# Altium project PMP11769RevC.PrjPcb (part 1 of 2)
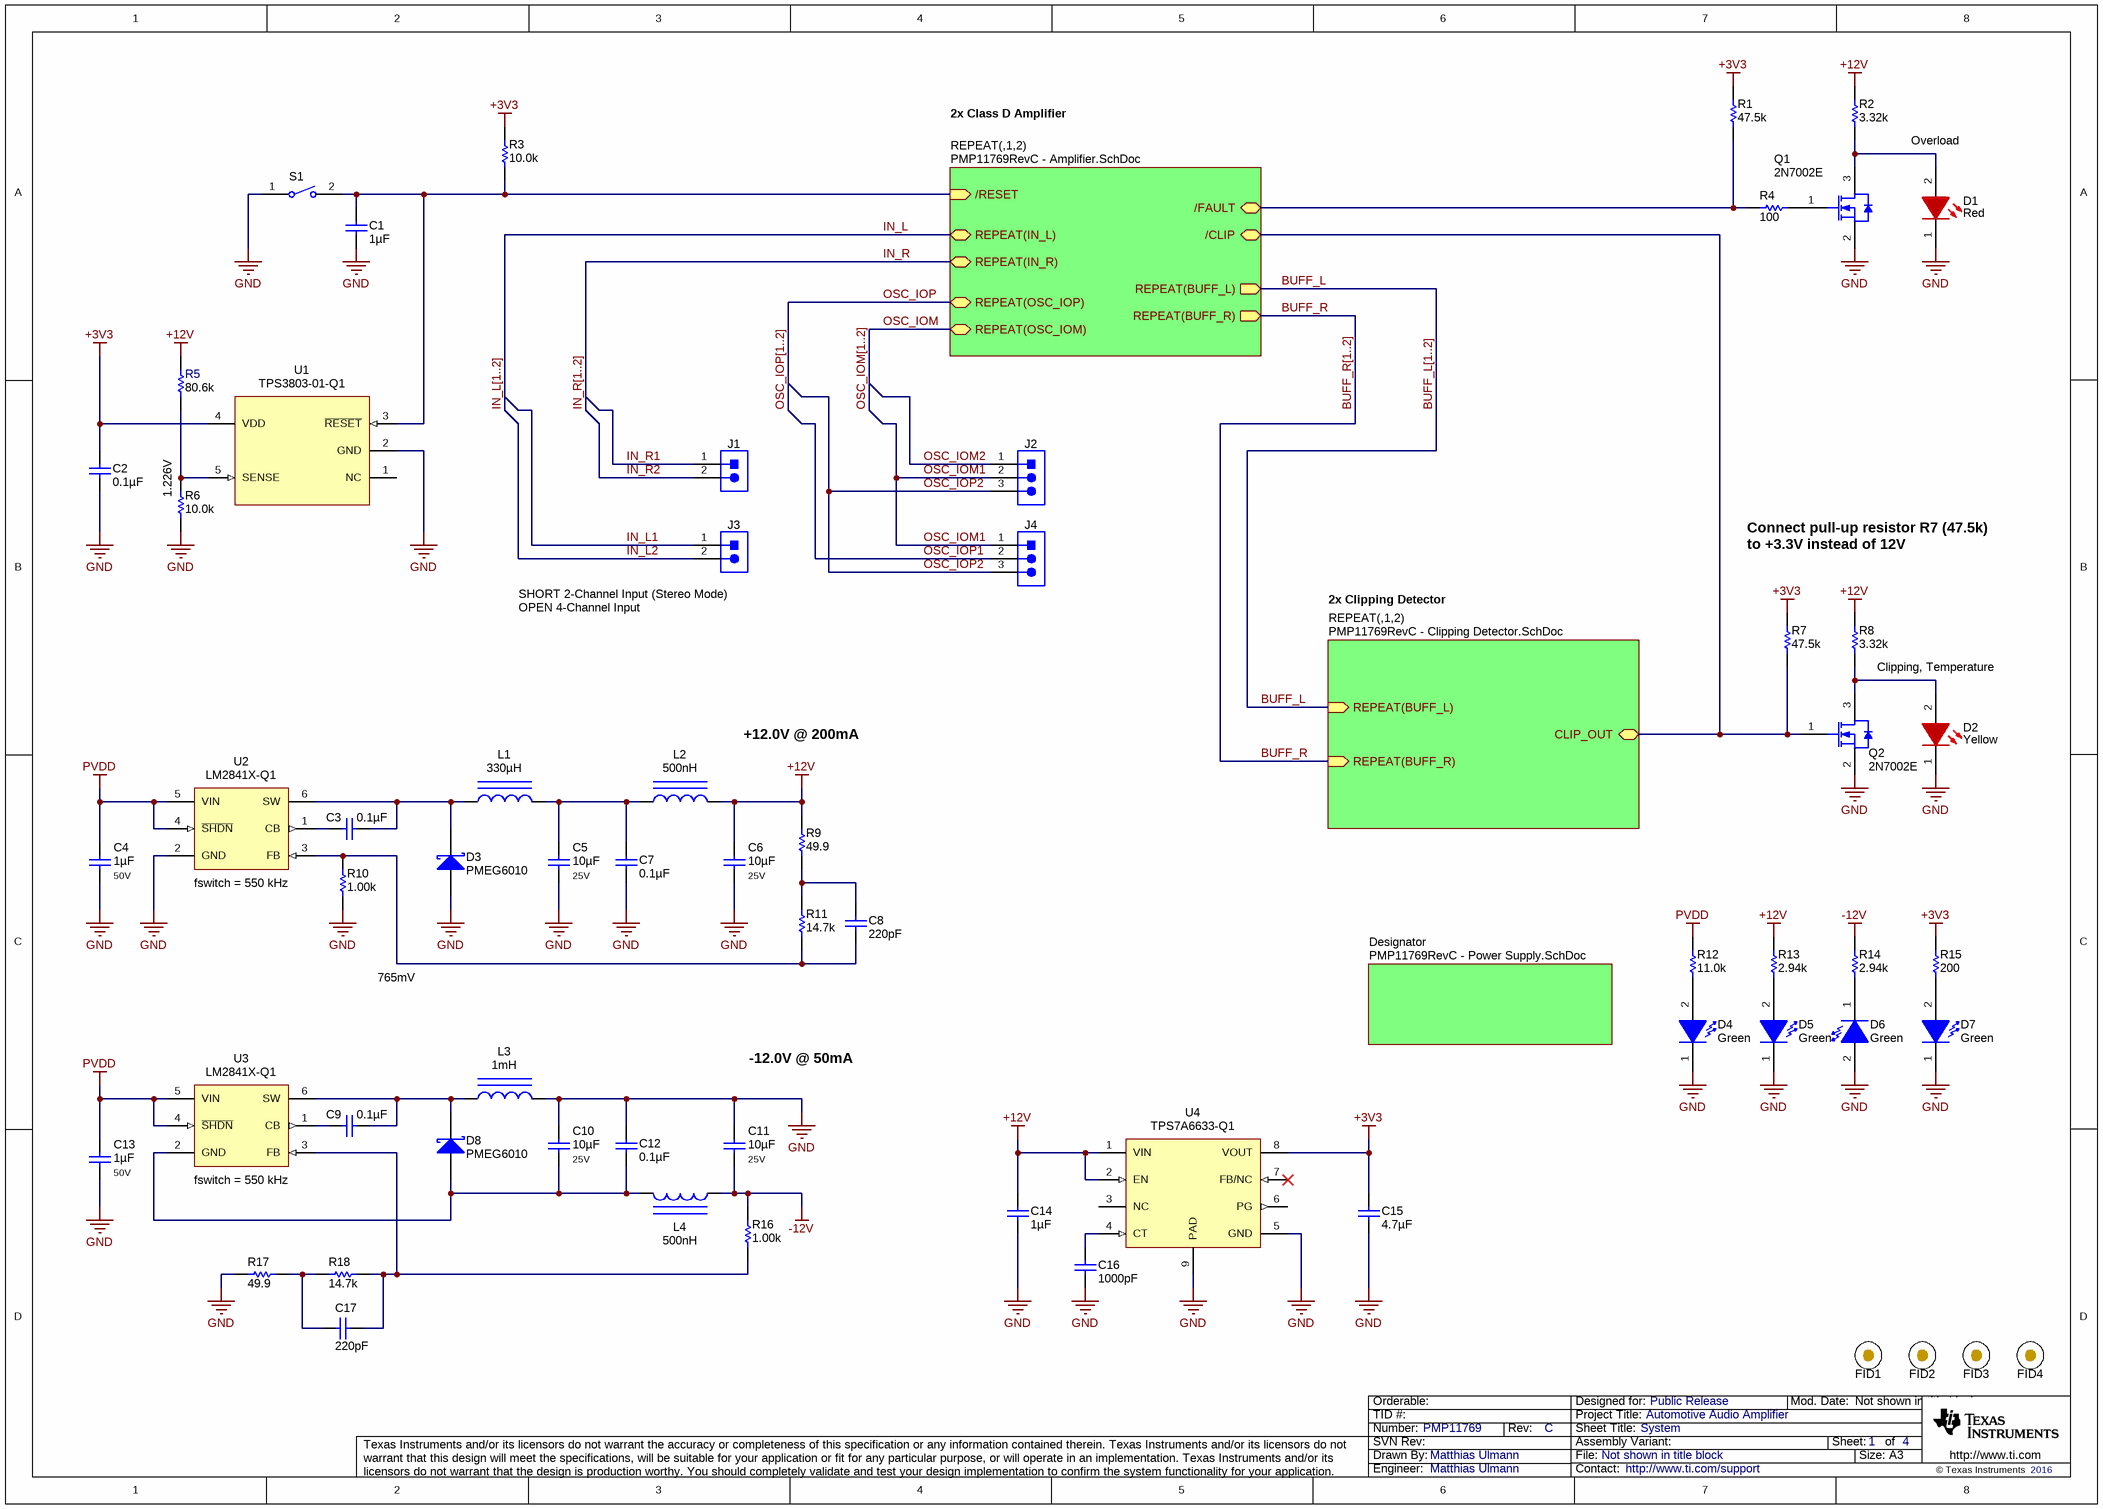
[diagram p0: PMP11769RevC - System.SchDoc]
CopyrightYear: 2016; PCB_Layout: M. Ulmann; PCB_Rev: C; PRJ_Customer: Public Release; PRJ_Engineer: Matthias Ulmann; PRJ_Number: PMP11769; PRJ_Title: Automotive Audio Amplifier; SCH_Rev: C; TechSupport: http://www.ti.com/support
4 sheets, 451 parts. Net scope: hierarchical (ports join the sheet entries above them; power ports are global).
Board file: PMP11769RevC.PcbDoc
Sheets:
  PMP11769RevC - System.SchDoc
    1 = PMP11769RevC - Amplifier.SchDoc
    2 = PMP11769RevC - Amplifier.SchDoc
    Designator = PMP11769RevC - Power Supply.SchDoc
    1 = PMP11769Revc - Clipping Detector.SchDoc
    2 = PMP11769Revc - Clipping Detector.SchDoc

## Sheet PMP11769RevC - System.SchDoc: System
size A3; Date: Not shown in title block; ApprovedBy: Not shown in title block; CheckedBy: Not shown in title block; Author: Not shown in title block; CompanyName: Not shown in title block; DrawnBy: Matthias Ulmann; Engineer: Not shown in title block; Organization: Not shown in title block; Address1: Not shown in title block; Address2: Not shown in title block; Address3: Not shown in title block; Address4: Not shown in title block; DocumentNumber: 1; Revision: Use project parameter SCH_Rev; SheetNumber: 1; SheetTotal: 4; PageSetup: Record=PageOptions¦CenterHorizontal=True¦CenterVertical=True¦PrintScale=1.00¦XCorrection=1.00¦YCorrection=1.00¦PrintKind=0¦BorderSize=5000000¦LeftOffset=0¦BottomOffset=0¦Orientation=2¦PaperLength=1000¦PaperWidth=1000¦Scale=100¦PaperSource=15¦PrintQuality=600¦MediaType=1¦DitherType=10¦PaperKind=Letter¦PrintScaleMode=1

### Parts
C1  ValueDisplayed: 1µF  [0603]  (hidden comment: C1608X7R1E105K080AB)
C2  ValueDisplayed: 0.1µF  [0603]  (hidden comment: C1608X7R1H104K)
C3  ValueDisplayed: 0.1µF  [0603]  (hidden comment: C1608X7R1H104K)
C4  ValueDisplayed: 1µF  Value2: 50V  [1206]  (hidden comment: C3216X7R1H105K)
C5  ValueDisplayed: 10µF  Value2: 25V  [1210]  (hidden comment: C3225X7R1E106M)
C6  ValueDisplayed: 10µF  Value2: 25V  [1210]  (hidden comment: C3225X7R1E106M)
C7  ValueDisplayed: 0.1µF  [0603]  (hidden comment: C1608X7R1H104K)
C8  ValueDisplayed: 220pF  [0603]  (hidden comment: C1608C0G1H221J)
C9  ValueDisplayed: 0.1µF  [0603]  (hidden comment: C1608X7R1H104K)
C10  ValueDisplayed: 10µF  Value2: 25V  [1210]  (hidden comment: C3225X7R1E106M)
C11  ValueDisplayed: 10µF  Value2: 25V  [1210]  (hidden comment: C3225X7R1E106M)
C12  ValueDisplayed: 0.1µF  [0603]  (hidden comment: C1608X7R1H104K)
C13  ValueDisplayed: 1µF  Value2: 50V  [1206]  (hidden comment: C3216X7R1H105K)
C14  ValueDisplayed: 1µF  [0603]  (hidden comment: C1608X7R1E105K080AB)
C15  ValueDisplayed: 4.7µF  [0805_HV]  (hidden comment: C2012X7R1A475M)
C16  ValueDisplayed: 1000pF  [0603]  (hidden comment: C1608X7R1H102K)
C17  ValueDisplayed: 220pF  [0603]  (hidden comment: C1608C0G1H221J)
D1  value Red  [551-0403_Red]  (hidden comment: 551-0303F)
D2  value Yellow  [551-0403_Red]  (hidden comment: 551-0303F)
D3  PMEG6010  [SOD-123F]
D4  value Green  [WL-SMCW_GREEN]  (hidden comment: 150060GS75000)
D5  value Green  [WL-SMCW_GREEN]  (hidden comment: 150060GS75000)
D6  value Green  [WL-SMCW_GREEN]  (hidden comment: 150060GS75000)
D7  value Green  [WL-SMCW_GREEN]  (hidden comment: 150060GS75000)
D8  PMEG6010  [SOD-123F]
FID1  Fiducial  [Fiducial10-30]  (value not drawn)
FID2  Fiducial  [Fiducial10-30]  (value not drawn)
FID3  Fiducial  [Fiducial10-30]  (value not drawn)
FID4  Fiducial  [Fiducial10-30]  (value not drawn)
J1  61300211121  [WURTH_61300211121]  (value not drawn)
J2  61300311121  [WURTH_61300311121]  (value not drawn)
J3  61300211121  [WURTH_61300211121]  (value not drawn)
J4  61300311121  [WURTH_61300311121]  (value not drawn)
L1  ValueDisplayed: 330µH  [LPS6235]  (hidden comment: LPS6235-334MLB)
L2  ValueDisplayed: 500nH  [XPL2010]  (hidden comment: XPL2010-501MLB)
L3  ValueDisplayed: 1mH  [LPS4012]  (hidden comment: LPS4012-105MLB)
L4  ValueDisplayed: 500nH  [XPL2010]  (hidden comment: XPL2010-501MLB)
Q1  2N7002E  [SOT-23]
Q2  2N7002E  [SOT-23]
R1  ValueDisplayed: 47.5k  [0603]  (hidden comment: CRCW060347K5FKEA)
R2  ValueDisplayed: 3.32k  [0603]  (hidden comment: CRCW06033K32FKEA)
R3  ValueDisplayed: 10.0k  [0603]  (hidden comment: CRCW060310K0FKEA)
R4  ValueDisplayed: 100  [0603]  (hidden comment: CRCW0603100RFKEA)
R5  ValueDisplayed: 80.6k  [0603]  (hidden comment: CRCW060380K6FKEA)
R6  ValueDisplayed: 10.0k  [0603]  (hidden comment: CRCW060310K0FKEA)
R7  ValueDisplayed: 47.5k  [0603]  (hidden comment: CRCW060347K5FKEA)
R8  ValueDisplayed: 3.32k  [0603]  (hidden comment: CRCW06033K32FKEA)
R9  ValueDisplayed: 49.9  [0603]  (hidden comment: CRCW060349R9FKEA)
R10  ValueDisplayed: 1.00k  [0603]  (hidden comment: CRCW06031K00FKEA)
R11  ValueDisplayed: 14.7k  [0603]  (hidden comment: CRCW060314K7FKEA)
R12  ValueDisplayed: 11.0k  [0603]  (hidden comment: CRCW060311K0FKEA)
R13  ValueDisplayed: 2.94k  [0603]  (hidden comment: CRCW06032K94FKEA)
R14  ValueDisplayed: 2.94k  [0603]  (hidden comment: CRCW06032K94FKEA)
R15  ValueDisplayed: 200  [0603]  (hidden comment: CRCW0603200RFKEA)
R16  ValueDisplayed: 1.00k  [0603]  (hidden comment: CRCW06031K00FKEA)
R17  ValueDisplayed: 49.9  [0603]  (hidden comment: CRCW060349R9FKEA)
R18  ValueDisplayed: 14.7k  [0603]  (hidden comment: CRCW060314K7FKEA)
S1  431256038716  [SW_1825027-2]  (value not drawn)
U1  TPS3803-01-Q1  [DCK0005A_N]
U2  LM2841X-Q1  [MK06A_N]
U3  LM2841X-Q1  [MK06A_N]
U4  TPS7A6633-Q1  [DGN0008D_N]

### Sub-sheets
Designator = PMP11769RevC - Power Supply.SchDoc: no entries
REPEAT(,1,2) = PMP11769RevC - Amplifier.SchDoc: /FAULT, /CLIP, /RESET (in), REPEAT(OSC_IOP) (bidir), REPEAT(OSC_IOM) (bidir), REPEAT(BUFF_L) (out), REPEAT(BUFF_R) (out), REPEAT(IN_L), REPEAT(IN_R)
REPEAT(,1,2) = PMP11769RevC - Clipping Detector.SchDoc: CLIP_OUT, REPEAT(BUFF_R) (in), REPEAT(BUFF_L) (in)

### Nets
+3V3: C2.2 C15.1 R1.2 R3.2 R7.2 R15.2 U1.4(VDD) U4.8(VOUT)
+12V: C6.1 C14.1 L2.2 R2.2 R5.2 R8.2 R9.2 R13.2 U4.1(VIN) U4.2(EN)
-12V: C11.2 L4.2 R14.2 R16.2
GND: C1.2 C2.1 C4.2 C5.2 C6.2 C7.1 C10.1 C11.1 C12.2 C13.2 C14.2 C15.2 C16.2 D1.1(K) D2.1(K) D3.2(A) D4.1(K) D5.1(K) D6.2(A) D7.1(K) L3.2 Q1.2(S) Q2.2(S) R6.1 R10.1 R17.1 S1.1 U1.2(GND) U2.2(GND) U4.5(GND) U4.9(PAD)
PVDD: C4.1 C13.1 R12.2 U2.4(~{SHDN}) U2.5(VIN) U3.4(~{SHDN}) U3.5(VIN)
/CLIP: Q2.1(G) R7.1 ; sheet REPEAT(,1,2)//CLIP, sheet REPEAT(,1,2)/CLIP_OUT
/FAULT: R1.1 R4.1 ; sheet REPEAT(,1,2)//FAULT
/RESET: C1.1 R3.1 S1.2 U1.3(~{RESET}) ; sheet REPEAT(,1,2)//RESET
BUFF_L: sheet REPEAT(,1,2)/REPEAT(BUFF_L), sheet REPEAT(,1,2)/REPEAT(BUFF_L)
BUFF_R: sheet REPEAT(,1,2)/REPEAT(BUFF_R), sheet REPEAT(,1,2)/REPEAT(BUFF_R)
IN_L1: J3.1
IN_L2: J3.2
IN_R1: J1.1
IN_R2: J1.2
OSC_IOM1: J2.2 J4.1
OSC_IOM2: J2.1
OSC_IOP1: J4.2
OSC_IOP2: J2.3 J4.3
NetC3_1: C3.1 D3.1(K) L1.1 U2.6(SW)
NetC3_2: C3.2 U2.1(CB)
NetC5_1: C5.1 C7.2 L1.2 L2.1
NetC8_1: C8.1 R9.1 R11.2
NetC8_2: C8.2 R10.2 R11.1 U2.3(FB)
NetC9_1: C9.1 D8.1(K) L3.1 U3.6(SW)
NetC9_2: C9.2 U3.1(CB)
NetC10_2: C10.2 C12.1 D8.2(A) L4.1 U3.2(GND)
NetC16_1: C16.1 U4.4(CT)
NetC17_1: C17.1 R17.2 R18.2
NetC17_2: C17.2 R16.1 R18.1 U3.3(FB)
NetD1_2: D1.2(A) Q1.3(D) R2.1
NetD2_2: D2.2(A) Q2.3(D) R8.1
NetD4_2: D4.2(A) R12.1
NetD5_2: D5.2(A) R13.1
NetD6_1: D6.1(K) R14.1
NetD7_2: D7.2(A) R15.1
NetQ1_1: Q1.1(G) R4.2
NetR5_1: R5.1 R6.2 U1.5(SENSE)

Not connected (* = marked no-connect by the designer): U1 1(NC); U4 3(NC) 6(PG) 7(FB/NC)*

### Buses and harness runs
bus BUFF_L[1..2]
bus BUFF_R[1..2]
bus IN_L[1..2]
bus IN_R[1..2]
bus OSC_IOM[1..2]
bus OSC_IOP[1..2]

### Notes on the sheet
- 2x Class D Amplifier
- Overload
- (near R6) 1.226V
- Connect pull-up resistor R7 (47.5k)
  to +3.3V instead of 12V
- (near J3) SHORT	2-Channel Input (Stereo Mode)
  OPEN	4-Channel Input
- 2x Clipping Detector
- (near R8) Clipping, Temperature
- +12.0V @ 200mA
- (near U2) fswitch = 550 kHz
- 765mV
- -12.0V @ 50mA
- (near U3) fswitch = 550 kHz

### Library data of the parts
C1 C14 = C1608X7R1E105K080AB: CAP, CERM, 1 µF, 25 V, +/- 10%, X7R, 0603; Manufacturer: TDK; Polarized: N; CompType: Capacitor; Value: 1uF; U/M: EA; Cap_F: 0.000001; Tolerance_%: 10; Value1: Unknown; VDC_V: 25; Value2: 25V; TaMin_C: -55; TaMax_C: 125; AEC Category: Q200
C2 C3 C7 C9 C12 = C1608X7R1H104K: CAP, CERM, 0.1 µF, 50 V, +/- 10%, X7R, 0603; Manufacturer: TDK; Polarized: N; CompType: Capacitor; Value: 0.1uF; U/M: EA; Cap_F: 0.0000001; Tolerance_%: 10; ESR_ohm: 0.017; Value1: 0.017 ohm; VDC_V: 50; Value2: 50V; TaMin_C: -55; TaMax_C: 125; AEC Category: Q200
C4 C13 = C3216X7R1H105K: CAP, CERM, 1 µF, 50 V, +/- 10%, X7R, 1206; Manufacturer: TDK; Polarized: N; CompType: Capacitor; Value: 1uF; U/M: EA; Cap_F: 0.000001; Tolerance_%: 10; ESR_ohm: 0.01; Value1: 0.01 ohm; VDC_V: 50; IRMS_A: 3.2; TaMin_C: -55; TaMax_C: 125; AEC Category: Q200
C5 C6 C10 C11 = C3225X7R1E106M: CAP, CERM, 10 µF, 25 V, +/- 20%, X7R, 1210; Manufacturer: TDK; Polarized: N; CompType: Capacitor; Value: 10uF; U/M: EA; Cap_F: 0.00001; Tolerance_%: 20; ESR_ohm: 0.0027; Value1: 0.0027 ohm; VDC_V: 25; IRMS_A: 3; TaMin_C: -55; TaMax_C: 125; AEC Category: Q200
C8 C17 = C1608C0G1H221J: CAP, CERM, 220 pF, 50 V, +/- 5%, C0G/NP0, 0603; Manufacturer: TDK; Polarized: N; CompType: Capacitor; Value: 220pF; U/M: EA; Cap_F: 0.00000000022; Tolerance_%: 5; ESR_ohm: 0.0831; Value1: 0.0831 ohm; VDC_V: 50; Value2: 50V; TaMin_C: -55; TaMax_C: 125; AEC Category: Q200
C15 = C2012X7R1A475M: CAP, CERM, 4.7 µF, 10 V, +/- 20%, X7R, 0805; Manufacturer: TDK; Polarized: N; CompType: Capacitor; Value: 4.7uF; U/M: EA; Cap_F: 0.0000047; Tolerance_%: 20; Value1: Unknown; VDC_V: 10; Value2: 10V; TaMin_C: -55; TaMax_C: 125; Cap_Case: 0805; AEC Category: Q200
C16 = C1608X7R1H102K: CAP, CERM, 1000 pF, 50 V, +/- 10%, X7R, 0603; Manufacturer: TDK; Polarized: N; CompType: Capacitor; Value: 1000pF; U/M: EA; Cap_F: 0.000000001; Tolerance_%: 10; ESR_ohm: 0.24; Value1: 0.24 ohm; VDC_V: 50; Value2: 50V; TaMin_C: -55; TaMax_C: 125; AEC Category: Q200
D1 = 551-0403F: LED, Yellow, TH; Manufacturer: Dialight; SymbolCreator: Altium; Vf_V: 2; Value2: 2V; Io_A: 0.01; Vr_V: 3; Tjmax_C: 85; Value1: W; Angle: 45; U/M: EA
D2 = 551-0403F: LED, Yellow, TH; Manufacturer: Dialight; SymbolCreator: Altium; Vf_V: 2; Value2: 2V; Io_A: 0.01; Vr_V: 3; Tjmax_C: 85; Value1: W; Angle: 45; Color: Red; U/M: EA
D3 D8 = PMEG6010CEH,115: Diode, Schottky, 60 V, 1 A, SOD-123F; Manufacturer: NXP Semiconductor; U/M: EA; Vf_V: 0.57; Value: 60V; Value1: 1A; Value2: 0.57V; Io_A: 1; Vr_V: 60; TJmax_C: 150; AEC Category: Q101
D4-D7 = 150060GS75000: LED, Green, SMD; Manufacturer: Wurth Elektronik; Type: InGaN; Vf_V: 3.2; Value2: 3.2V; Io_A: 0.02; Tjmax_C: 85; Value1: W; Angle: 140; U/M: EA
FID1-FID4 = Fiducial: Fiducial mark.  There is nothing to buy or mount.; SymbolCreator: codlsc
J1 J3 = 61300211121: Header, 2.54 mm, 2x1, Gold, TH; Manufacturer: Wurth Elektronik; SymbolCreator: a0412235; U/M: EA
J2 J4 = 61300311121: Header, 2.54 mm, 3x1, Gold, TH; Manufacturer: Wurth Elektronik; SymbolCreator: a0799628
L1 = LPS6235-334MLB: Inductor, Shielded Drum Core, Ferrite, 330 µH, 0.3 A, 1.2 ohm, SMD; Manufacturer: Coilcraft; Value: 330uH; Ind_H: 330.0E-6; Imax_A: 0.3; Irms: 0.5A @ 40C rise; Isat: 0.3A @ 30% inductance drop; DCR_ohm: 1.2; Value1: 1.2 ohm; Value2: 0.3A; AEC Category: Q200
L2 L4 = XPL2010-501MLB: Inductor, Shielded, Composite, 500 nH, 2.3 A, 0.04 ohm, SMD; Manufacturer: Coilcraft; Value: 500nH; Ind_H: 500.0E-9; Imax_A: 2.3; Irms: 2.3A @ 40C rise; Isat: 2.64A @ 30% inductance drop; DCR_ohm: 0.04; Value2: 2.3A; AEC Category: Q200
L3 = LPS4012-105MLB: Inductor, Shielded Drum Core, Ferrite, 1 mH, 0.1 A, 21.5 ohm, SMD; Manufacturer: Coilcraft; Value: 1mH; Ind_H: 1.0E-3; Imax_A: 0.1; Irms: 0.13A @ 40C rise; Isat: 0.095A @ 30% inductance drop; DCR_ohm: 21.5; Value2: 0.1A; AEC Category: Q200
Q1 Q2 = 2N7002E-T1-E3: MOSFET, N-CH, 60 V, 0.24 A, SOT-23; Manufacturer: Vishay-Siliconix; Alternate Manufacturer: None; U/M: EA; ChType: N; Value: 60V; VdsMax_V: 60; Value1: 1.8 ohm; Rdson45_ohm: 1.8; Value2: 0.4 nC; QgTyp_nC: 0.4; Vgs_V: 20; IdsMax_A: 0.24; AEC Category: Q101
R1 R7 = CRCW060347K5FKEA: RES, 47.5 k, 1%, 0.1 W, 0603; Manufacturer: Vishay-Dale; CompType: Resistor; Value: 47.5k; Res_ohm: 47500; Value_Code: 47k5; Tolerance_%: 1; Power_W: 0.1; Value2: 0.1W; VDC_V: 75; TempCo: 100 ppm/C; EIA_Code: E96; U/M: EA; AEC Category: Q200
R2 R8 = CRCW06033K32FKEA: RES, 3.32 k, 1%, 0.1 W, 0603; Manufacturer: Vishay-Dale; CompType: Resistor; Value: 3.32k; Res_ohm: 3320; Value_Code: 3k32; Tolerance_%: 1; Power_W: 0.1; Value2: 0.1W; VDC_V: 75; TempCo: 100 ppm/C; EIA_Code: E96; U/M: EA; AEC Category: Q200
R3 R6 = CRCW060310K0FKEA: RES, 10.0 k, 1%, 0.1 W, 0603; Manufacturer: Vishay-Dale; CompType: Resistor; Value: 10.0k; Res_ohm: 10000; Value_Code: 10k0; Tolerance_%: 1; Power_W: 0.1; Value2: 0.1W; VDC_V: 75; TempCo: 100 ppm/C; EIA_Code: E96; U/M: EA; AEC Category: Q200
R4 = CRCW0603100RFKEA: RES, 100, 1%, 0.1 W, 0603; Manufacturer: Vishay-Dale; CompType: Resistor; Value: 100; Value_Code: 100R; Tolerance_%: 1; Power_W: 0.1; Value2: 0.1W; VDC_V: 75; TempCo: 100 ppm/C; EIA_Code: E96; U/M: EA; AEC Category: Q200
R5 = CRCW060380K6FKEA: RES, 80.6 k, 1%, 0.1 W, 0603; Manufacturer: Vishay-Dale; CompType: Resistor; Value: 80.6k; Res_ohm: 80600; Value_Code: 80k6; Tolerance_%: 1; Power_W: 0.1; Value2: 0.1W; VDC_V: 75; TempCo: 100 ppm/C; EIA_Code: E96; U/M: EA; AEC Category: Q200
R9 R17 = CRCW060349R9FKEA: RES, 49.9, 1%, 0.1 W, 0603; Manufacturer: Vishay-Dale; CompType: Resistor; Value: 49.9; Value_Code: 49R9; Tolerance_%: 1; Power_W: 0.1; Value2: 0.1W; VDC_V: 75; TempCo: 100 ppm/C; EIA_Code: E96; U/M: EA; AEC Category: Q200
R10 R16 = CRCW06031K00FKEA: RES, 1.00 k, 1%, 0.1 W, 0603; Manufacturer: Vishay-Dale; CompType: Resistor; Value: 1.00k; Res_ohm: 1000; Value_Code: 1k00; Tolerance_%: 1; Power_W: 0.1; Value2: 0.1W; VDC_V: 75; TempCo: 100 ppm/C; EIA_Code: E96; U/M: EA; AEC Category: Q200
R11 R18 = CRCW060314K7FKEA: RES, 14.7 k, 1%, 0.1 W, 0603; Manufacturer: Vishay-Dale; CompType: Resistor; Value: 14.7k; Res_ohm: 14700; Value_Code: 14k7; Tolerance_%: 1; Power_W: 0.1; Value2: 0.1W; VDC_V: 75; TempCo: 100 ppm/C; EIA_Code: E96; U/M: EA; AEC Category: Q200
R12 = CRCW060311K0FKEA: RES, 11.0 k, 1%, 0.1 W, 0603; Manufacturer: Vishay-Dale; CompType: Resistor; Value: 11.0k; Res_ohm: 11000; Value_Code: 11k0; Tolerance_%: 1; Power_W: 0.1; Value2: 0.1W; VDC_V: 75; TempCo: 100 ppm/C; EIA_Code: E96; U/M: EA; AEC Category: Q200
R13 R14 = CRCW06032K94FKEA: RES, 2.94 k, 1%, 0.1 W, 0603; Manufacturer: Vishay-Dale; CompType: Resistor; Value: 2.94k; Res_ohm: 2940; Value_Code: 2k94; Tolerance_%: 1; Power_W: 0.1; Value2: 0.1W; VDC_V: 75; TempCo: 100 ppm/C; EIA_Code: E96; U/M: EA; AEC Category: Q200
R15 = CRCW0603200RFKEA: RES, 200, 1%, 0.1 W, 0603; Manufacturer: Vishay-Dale; CompType: Resistor; Value: 200; Value_Code: 200R; Tolerance_%: 1; Power_W: 0.1; Value2: 0.1W; VDC_V: 75; TempCo: 100 ppm/C; EIA_Code: E96; U/M: EA; AEC Category: Q200
S1 = 1825027-2: Switch, SPST-NO, Off-Mom, 0.05 A, 12 V, R/A, TH; Manufacturer: Wurth Elektronik; SymbolCreator: a0799628; VDC_V: 12; PositionCount: 1; CurrentRating_mA: 50
U1 = TPS3803-01QDCKRQ1: VOLTAGE DETECTOR, DCK0005A; Manufacturer: Texas Instruments; SymbolCreator: a0411947; CompType: IC; U/M: EA
U2 U3 = LM2841XMK-ADJL: 300 mA/600 mA up to 42V Input Step-Down DC/DC Regulator, 6-pin Tiny SOT23; PartNumber: LM2841XQMK/NOPB; Manufacturer: Texas Instruments; PackageTopMarking: STFB*XTT; PowerWise: N; CompType: MiscPower
U4 = TPS7A6633QDGNRQ1: High-Voltage Ultralow-Iq Low-Dropout Regulator, DGN0008D; Manufacturer: Texas Instruments; SymbolCreator: a0411947; CompType: IC; U/M: EA

## Sheet PMP11769RevC - Amplifier.SchDoc: Amplifier
size A3; Date: Not shown in title block; ApprovedBy: Not shown in title block; CheckedBy: Not shown in title block; Author: Not shown in title block; CompanyName: Not shown in title block; DrawnBy: Matthias Ulmann; Engineer: Not shown in title block; Organization: Not shown in title block; Address1: Not shown in title block; Address2: Not shown in title block; Address3: Not shown in title block; Address4: Not shown in title block; DocumentNumber: 2; Revision: Use project parameter SCH_Rev; SheetNumber: 2; SheetTotal: 4; PageSetup: Record=PageOptions¦CenterHorizontal=True¦CenterVertical=True¦PrintScale=1.00¦XCorrection=1.00¦YCorrection=1.00¦PrintKind=0¦BorderSize=5000000¦LeftOffset=0¦BottomOffset=0¦Orientation=2¦PaperLength=1000¦PaperWidth=1000¦Scale=100¦PaperSource=15¦PrintQuality=600¦MediaType=1¦DitherType=10¦PaperKind=Letter¦PrintScaleMode=1
Used 2 times, as channels 1, 2. Parts and nets are listed once, with the designators drawn on the sheet.
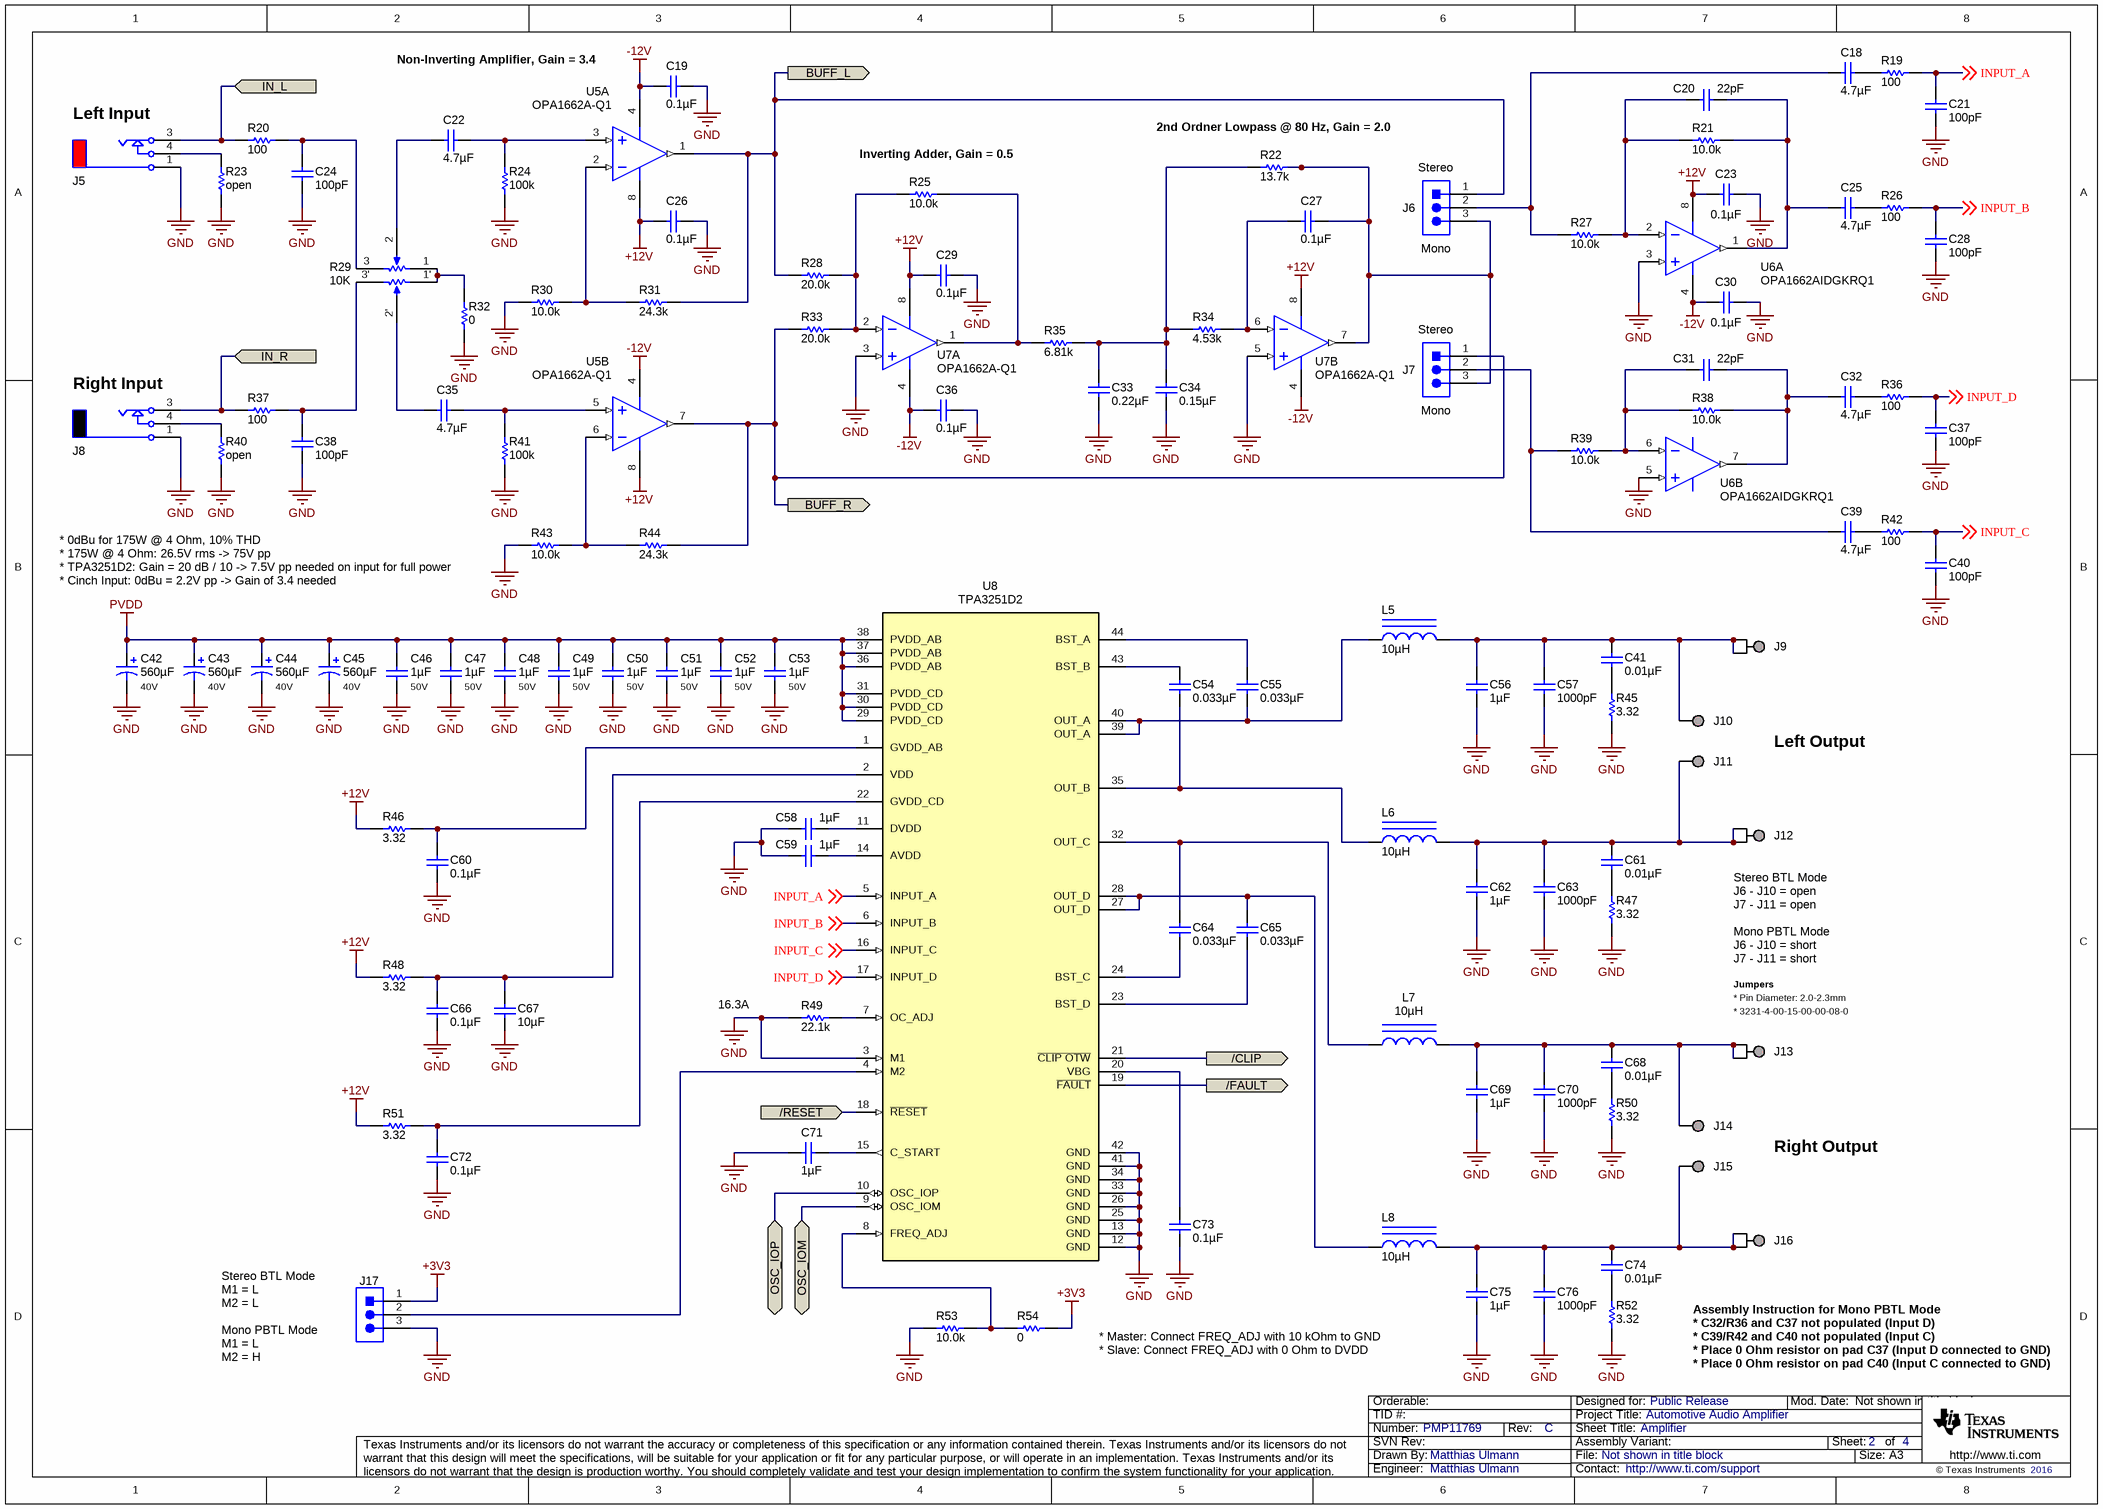
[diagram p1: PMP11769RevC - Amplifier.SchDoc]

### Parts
C18  ValueDisplayed: 4.7µF  [R82_720x720x1300]  (hidden comment: R82CC4470Z330J)
C19  ValueDisplayed: 0.1µF  [0603]  (hidden comment: C1608X7R1H104K)
C20  ValueDisplayed: 22pF  [0402]  (hidden comment: C1005C0G1H220J050BA)
C21  ValueDisplayed: 100pF  [0603]  (hidden comment: C1608C0G1H101J)
C22  ValueDisplayed: 4.7µF  [R82_720x720x1300]  (hidden comment: R82CC4470Z330J)
C23  ValueDisplayed: 0.1µF  [0603]  (hidden comment: C1608X7R1H104K)
C24  ValueDisplayed: 100pF  [0603]  (hidden comment: C1608C0G1H101J)
C25  ValueDisplayed: 4.7µF  [R82_720x720x1300]  (hidden comment: R82CC4470Z330J)
C26  ValueDisplayed: 0.1µF  [0603]  (hidden comment: C1608X7R1H104K)
C27  ValueDisplayed: 0.1µF  [R82_720x250x650]  (hidden comment: R82DC3100DQ50J)
C28  ValueDisplayed: 100pF  [0603]  (hidden comment: C1608C0G1H101J)
C29  ValueDisplayed: 0.1µF  [0603]  (hidden comment: C1608X7R1H104K)
C30  ValueDisplayed: 0.1µF  [0603]  (hidden comment: C1608X7R1H104K)
C31  ValueDisplayed: 22pF  [0402]  (hidden comment: C1005C0G1H220J050BA)
C32  ValueDisplayed: 4.7µF  [R82_720x720x1300]  (hidden comment: R82CC4470Z330J)
C33  ValueDisplayed: 0.22µF  [R82_720x250x650]  (hidden comment: R82DC3220DQ60J)
C34  ValueDisplayed: 0.15µF  [R82_720x250x650]  (hidden comment: R82DC3150AA60J)
C35  ValueDisplayed: 4.7µF  [R82_720x720x1300]  (hidden comment: R82CC4470Z330J)
C36  ValueDisplayed: 0.1µF  [0603]  (hidden comment: C1608X7R1H104K)
C37  ValueDisplayed: 100pF  [0603]  (hidden comment: C1608C0G1H101J)
C38  ValueDisplayed: 100pF  [0603]  (hidden comment: C1608C0G1H101J)
C39  ValueDisplayed: 4.7µF  [R82_720x720x1300]  (hidden comment: R82CC4470Z330J)
C40  ValueDisplayed: 100pF  [0603]  (hidden comment: C1608C0G1H101J)
C41  ValueDisplayed: 0.01µF  [0603]  (hidden comment: C1608X7R1H103K)
C42  ValueDisplayed: 560µF  Value2: 40V  [PW_1800x2000]  (hidden comment: UPW1G561MHDANE)
C43  ValueDisplayed: 560µF  Value2: 40V  [PW_1800x2000]  (hidden comment: UPW1G561MHDANE)
C44  ValueDisplayed: 560µF  Value2: 40V  [PW_1800x2000]  (hidden comment: UPW1G561MHDANE)
C45  ValueDisplayed: 560µF  Value2: 40V  [PW_1800x2000]  (hidden comment: UPW1G561MHDANE)
C46  ValueDisplayed: 1µF  Value2: 50V  [0603]  (hidden comment: UMK107AB7105KA-T)
C47  ValueDisplayed: 1µF  Value2: 50V  [0603]  (hidden comment: UMK107AB7105KA-T)
C48  ValueDisplayed: 1µF  Value2: 50V  [0603]  (hidden comment: UMK107AB7105KA-T)
C49  ValueDisplayed: 1µF  Value2: 50V  [0603]  (hidden comment: UMK107AB7105KA-T)
C50  ValueDisplayed: 1µF  Value2: 50V  [0603]  (hidden comment: UMK107AB7105KA-T)
C51  ValueDisplayed: 1µF  Value2: 50V  [0603]  (hidden comment: UMK107AB7105KA-T)
C52  ValueDisplayed: 1µF  Value2: 50V  [0603]  (hidden comment: UMK107AB7105KA-T)
C53  ValueDisplayed: 1µF  Value2: 50V  [0603]  (hidden comment: UMK107AB7105KA-T)
C54  ValueDisplayed: 0.033µF  [0603]  (hidden comment: GRM188R71H333KA61D)
C55  ValueDisplayed: 0.033µF  [0603]  (hidden comment: GRM188R71H333KA61D)
C56  ValueDisplayed: 1µF  [PHE426_1800x950x1750]  (hidden comment: PHE426HB7100JR06)
C57  ValueDisplayed: 1000pF  [0603]  (hidden comment: C1608C0G2A102J)
C58  ValueDisplayed: 1µF  [0603]  (hidden comment: C1608X7R1E105K080AB)
C59  ValueDisplayed: 1µF  [0603]  (hidden comment: C1608X7R1E105K080AB)
C60  ValueDisplayed: 0.1µF  [0603]  (hidden comment: C1608X7R1H104K)
C61  ValueDisplayed: 0.01µF  [0603]  (hidden comment: C1608X7R1H103K)
C62  ValueDisplayed: 1µF  [PHE426_1800x950x1750]  (hidden comment: PHE426HB7100JR06)
C63  ValueDisplayed: 1000pF  [0603]  (hidden comment: C1608C0G2A102J)
C64  ValueDisplayed: 0.033µF  [0603]  (hidden comment: GRM188R71H333KA61D)
C65  ValueDisplayed: 0.033µF  [0603]  (hidden comment: GRM188R71H333KA61D)
C66  ValueDisplayed: 0.1µF  [0603]  (hidden comment: C1608X7R1H104K)
C67  ValueDisplayed: 10µF  [1210]  (hidden comment: C3225X7R1E106M)
C68  ValueDisplayed: 0.01µF  [0603]  (hidden comment: C1608X7R1H103K)
C69  ValueDisplayed: 1µF  [PHE426_1800x950x1750]  (hidden comment: PHE426HB7100JR06)
C70  ValueDisplayed: 1000pF  [0603]  (hidden comment: C1608C0G2A102J)
C71  ValueDisplayed: 1µF  [0603]  (hidden comment: C1608X7R1E105K080AB)
C72  ValueDisplayed: 0.1µF  [0603]  (hidden comment: C1608X7R1H104K)
C73  ValueDisplayed: 0.1µF  [0603]  (hidden comment: C1608X7R1H104K)
C74  ValueDisplayed: 0.01µF  [0603]  (hidden comment: C1608X7R1H103K)
C75  ValueDisplayed: 1µF  [PHE426_1800x950x1750]  (hidden comment: PHE426HB7100JR06)
C76  ValueDisplayed: 1000pF  [0603]  (hidden comment: C1608C0G2A102J)
J5  971  [Keystone_971]  (value not drawn)
J6  61300311121  [WURTH_61300311121]  (value not drawn)
J7  61300311121  [WURTH_61300311121]  (value not drawn)
J8  972  [Keystone_972]  (value not drawn)
J9  TESTPOINT_2Pos  [HIRSCHMANN_973 582-101]  (value not drawn)
J10  Suggest using a net name here  [Harwin_H3492-01]  (value not drawn)
J11  Suggest using a net name here  [Harwin_H3492-01]  (value not drawn)
J12  TESTPOINT_2Pos  [HIRSCHMANN_973 582-100]  (value not drawn)
J13  TESTPOINT_2Pos  [HIRSCHMANN_973 582-101]  (value not drawn)
J14  Suggest using a net name here  [Harwin_H3492-01]  (value not drawn)
J15  Suggest using a net name here  [Harwin_H3492-01]  (value not drawn)
J16  TESTPOINT_2Pos  [HIRSCHMANN_973 582-100]  (value not drawn)
J17  61300311121  [WURTH_61300311121]  (value not drawn)
L5  ValueDisplayed: 10µH  [SER2918H]  (hidden comment: SER2918H-103KL)
L6  ValueDisplayed: 10µH  [SER2918H]  (hidden comment: SER2918H-103KL)
L7  ValueDisplayed: 10µH  [SER2918H]  (hidden comment: SER2918H-103KL)
L8  ValueDisplayed: 10µH  [SER2918H]  (hidden comment: SER2918H-103KL)
R19  ValueDisplayed: 100  [0603]  (hidden comment: CRCW0603100RFKEA)
R20  ValueDisplayed: 100  [0603]  (hidden comment: CRCW0603100RFKEA)
R21  ValueDisplayed: 10.0k  [0402]  (hidden comment: CRCW040210K0FKED)
R22  ValueDisplayed: 13.7k  [0603]  (hidden comment: CRCW060313K7FKEA)
R23  ValueDisplayed: open  [0603]  (hidden comment: CRCW06030000Z0EA)
R24  ValueDisplayed: 100k  [0603]  (hidden comment: CRCW0603100KFKEA)
R25  ValueDisplayed: 10.0k  [0603]  (hidden comment: CRCW060310K0FKEA)
R26  ValueDisplayed: 100  [0603]  (hidden comment: CRCW0603100RFKEA)
R27  ValueDisplayed: 10.0k  [0402]  (hidden comment: CRCW040210K0FKED)
R28  ValueDisplayed: 20.0k  [0603]  (hidden comment: CRCW060320K0FKEA)
R29  value 10K  [Bourns_PTD902]  (hidden comment: PTD902-2015F-A103)
R30  ValueDisplayed: 10.0k  [0603]  (hidden comment: CRCW060310K0FKEA)
R31  ValueDisplayed: 24.3k  [0603]  (hidden comment: CRCW060324K3FKEA)
R32  ValueDisplayed: 0  [0603]  (hidden comment: CRCW06030000Z0EA)
R33  ValueDisplayed: 20.0k  [0603]  (hidden comment: CRCW060320K0FKEA)
R34  ValueDisplayed: 4.53k  [0603]  (hidden comment: CRCW06034K53FKEA)
R35  ValueDisplayed: 6.81k  [0603]  (hidden comment: CRCW06036K81FKEA)
R36  ValueDisplayed: 100  [0603]  (hidden comment: CRCW0603100RFKEA)
R37  ValueDisplayed: 100  [0603]  (hidden comment: CRCW0603100RFKEA)
R38  ValueDisplayed: 10.0k  [0402]  (hidden comment: CRCW040210K0FKED)
R39  ValueDisplayed: 10.0k  [0402]  (hidden comment: CRCW040210K0FKED)
R40  ValueDisplayed: open  [0603]  (hidden comment: CRCW06030000Z0EA)
R41  ValueDisplayed: 100k  [0603]  (hidden comment: CRCW0603100KFKEA)
R42  ValueDisplayed: 100  [0603]  (hidden comment: CRCW0603100RFKEA)
R43  ValueDisplayed: 10.0k  [0603]  (hidden comment: CRCW060310K0FKEA)
R44  ValueDisplayed: 24.3k  [0603]  (hidden comment: CRCW060324K3FKEA)
R45  ValueDisplayed: 3.32  [0603]  (hidden comment: CRCW06033R32FKEA)
R46  ValueDisplayed: 3.32  [0603]  (hidden comment: CRCW06033R32FKEA)
R47  ValueDisplayed: 3.32  [0603]  (hidden comment: CRCW06033R32FKEA)
R48  ValueDisplayed: 3.32  [0603]  (hidden comment: CRCW06033R32FKEA)
R49  ValueDisplayed: 22.1k  [0603]  (hidden comment: CRCW060322K1FKEA)
R50  ValueDisplayed: 3.32  [0603]  (hidden comment: CRCW06033R32FKEA)
R51  ValueDisplayed: 3.32  [0603]  (hidden comment: CRCW06033R32FKEA)
R52  ValueDisplayed: 3.32  [0603]  (hidden comment: CRCW06033R32FKEA)
R53  ValueDisplayed: 10.0k  [0603]  (hidden comment: CRCW060310K0FKEA)
R54  ValueDisplayed: 0  [0603]  (hidden comment: CRCW06030000Z0EA)
U5  OPA1662A-Q1  [D0008A_N]  (parts A,B of 2)
U6  OPA1662AIDGKRQ1  [DGK0008A_N]  (parts A,B of 2)
U7  OPA1662A-Q1  [D0008A_N]  (parts A,B of 2)
U8  TPA3251D2  [DDV0044D_N]

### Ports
/CLIP (out), /FAULT (out), /RESET (in), BUFF_L (out), BUFF_R (out), IN_L, IN_R, OSC_IOM (bidir), OSC_IOP (bidir)

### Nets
+3V3: J17.1 R54.1
+12V: C23.1 C26.1 C29.1 R46.2 R48.2 R51.2 U5.8(V+) U6.8(V+) U7.8(V+)
-12V: C19.1 C30.1 C36.1 U5.4(V-) U6.4(V-) U7.4(V-)
GND: C19.2 C21.2 C23.2 C24.2 C26.2 C28.2 C29.2 C30.2 C33.2 C34.2 C36.2 C37.2 C38.2 C40.2 C42.2(-) C43.2(-) C44.2(-) C45.2(-) C46.2 C47.2 C48.2 C49.2 C50.2 C51.2 C52.2 C53.2 C56.2 C57.2 C58.2 C59.2 C60.1 C62.2 C63.2 C66.1 C67.2 C69.2 C70.2 C71.1 C72.1 C73.2 C75.2 C76.2 J5.1(SLEEVE) J8.1(SLEEVE) J17.3 R23.1 R24.1 R30.2 R32.1 R40.1 R41.1 R43.2 R45.1 R47.1 R49.1 R50.1 R52.1 R53.1 U6.3(IN_A+) U6.5(IN_B+) U7.3(IN_A+) U7.5(IN_B+) U8.3(M1) U8.12(GND) U8.13(GND) U8.25(GND) U8.26(GND) U8.33(GND) U8.34(GND) U8.41(GND) U8.42(GND)
PVDD: C42.1(+) C43.1(+) C44.1(+) C45.1(+) C46.1 C47.1 C48.1 C49.1 C50.1 C51.1 C52.1 C53.1 U8.29(PVDD_CD) U8.30(PVDD_CD) U8.31(PVDD_CD) U8.36(PVDD_AB) U8.37(PVDD_AB) U8.38(PVDD_AB)
/CLIP: U8.21(~{CLIP_OTW}) ; port /CLIP
/FAULT: U8.19(~{FAULT}) ; port /FAULT
/RESET: U8.18(~{RESET}) ; port /RESET
BUFF_L: J6.1 R28.1 R31.2 U5.1(OUT_A) ; port BUFF_L
BUFF_R: J7.1 R33.1 R44.2 U5.7(OUT_B) ; port BUFF_R
IN_L: J5.3(TIP) R20.1 ; port IN_L
IN_R: J8.3(TIP) R37.1 ; port IN_R
INPUT_A: C21.1 R19.2 U8.5(INPUT_A) ; off-sheet INPUT_A
INPUT_B: C28.1 R26.2 U8.6(INPUT_B) ; off-sheet INPUT_B
INPUT_C: C40.1 R42.2 U8.16(INPUT_C) ; off-sheet INPUT_C
INPUT_D: C37.1 R36.2 U8.17(INPUT_D) ; off-sheet INPUT_D
OSC_IOM: U8.9(OSC_IOM) ; port OSC_IOM
OSC_IOP: U8.10(OSC_IOP) ; port OSC_IOP
NetC18_1: C18.1 R19.1
NetC18_2: C18.2 J6.2 R27.1
NetC20_1: C20.1 C25.2 R21.2 U6.1(OUT_A)
NetC20_2: C20.2 R21.1 R27.2 U6.2(IN_A-)
NetC22_1: C22.1 R24.2 U5.3(IN_A+)
NetC22_2: C22.2 R29.2
NetC24_1: C24.1 R20.2 R29.3
NetC25_1: C25.1 R26.1
NetC27_1: C27.1 J6.3 J7.3 R22.2 U7.7(OUT_B)
NetC27_2: C27.2 R34.2 U7.6(IN_B-)
NetC31_1: C31.1 C32.2 R38.2 U6.7(OUT_B)
NetC31_2: C31.2 R38.1 R39.2 U6.6(IN_B-)
NetC32_1: C32.1 R36.1
NetC33_1: C33.1 C34.1 R22.1 R34.1 R35.2
NetC35_1: C35.1 R41.2 U5.5(IN_B+)
NetC35_2: C35.2 R29.2'
NetC38_1: C38.1 R29.3' R37.2
NetC39_1: C39.1 R42.1
NetC39_2: C39.2 J7.2 R39.1
NetC41_1: C41.1 C56.1 C57.1 J9.1 J9.2 J10.1 L5.2
NetC41_2: C41.2 R45.2
NetC54_1: C54.1 U8.43(BST_B)
NetC54_2: C54.2 L6.2 U8.35(OUT_B)
NetC55_1: C55.1 U8.44(BST_A)
NetC55_2: C55.2 L5.1 U8.39(OUT_A) U8.40(OUT_A)
NetC58_1: C58.1 U8.11(DVDD)
NetC59_1: C59.1 U8.14(AVDD)
NetC60_2: C60.2 R46.1 U8.1(GVDD_AB)
NetC61_1: C61.1 C62.1 C63.1 J11.1 J12.1 J12.2 L6.1
NetC61_2: C61.2 R47.2
NetC64_1: C64.1 L7.1 U8.32(OUT_C)
NetC64_2: C64.2 U8.24(BST_C)
NetC65_1: C65.1 L8.2 U8.27(OUT_D) U8.28(OUT_D)
NetC65_2: C65.2 U8.23(BST_D)
NetC66_2: C66.2 C67.1 R48.1 U8.2(VDD)
NetC68_1: C68.1 C69.1 C70.1 J13.1 J13.2 J14.1 L7.2
NetC68_2: C68.2 R50.2
NetC71_2: C71.2 U8.15(C_START)
NetC72_2: C72.2 R51.1 U8.22(GVDD_CD)
NetC73_1: C73.1 U8.20(VBG)
NetC74_1: C74.1 C75.1 C76.1 J15.1 J16.1 J16.2 L8.1
NetC74_2: C74.2 R52.2
NetJ5_4: J5.4(TIP_SWITCH) R23.2
NetJ8_4: J8.4(TIP_SWITCH) R40.2
NetJ17_2: J17.2 U8.4(M2)
NetR25_1: R25.1 R28.2 R33.2 U7.2(IN_A-)
NetR25_2: R25.2 R35.1 U7.1(OUT_A)
NetR29_1: R29.1 R29.1' R32.2
NetR30_1: R30.1 R31.1 U5.2(IN_A-)
NetR43_1: R43.1 R44.1 U5.6(IN_B-)
NetR49_2: R49.2 U8.7(OC_ADJ)
NetR53_2: R53.2 R54.2 U8.8(FREQ_ADJ)

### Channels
1: designators end in _1; ports /CLIP=/CLIP /FAULT=/FAULT /RESET=/RESET BUFF_L=BUFF_L1 BUFF_R=BUFF_R1 IN_L=IN_L1 IN_R=IN_R1 OSC_IOM=OSC_IOM1 OSC_IOP=OSC_IOP1
2: designators end in _2; ports /CLIP=/CLIP /FAULT=/FAULT /RESET=/RESET BUFF_L=BUFF_L2 BUFF_R=BUFF_R2 IN_L=IN_L2 IN_R=IN_R2 OSC_IOM=OSC_IOM2 OSC_IOP=OSC_IOP2

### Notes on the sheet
- (near J5) Left Input
- Non-Inverting Amplifier, Gain = 3.4
- (near R25) Inverting Adder, Gain = 0.5
- (near R22) 2nd Ordner Lowpass @ 80 Hz, Gain = 2.0
- (near J6) Stereo
- (near J6) Mono
- (near J8) Right Input
- (near J7) Stereo
- (near J7) Mono
- * 0dBu for 175W @ 4 Ohm, 10% THD
  * 175W @ 4 Ohm: 26.5V rms -> 75V pp
  * TPA3251D2: Gain = 20 dB / 10 -> 7.5V pp needed on input for full power
  * Cinch Input: 0dBu = 2.2V pp -> Gain of 3.4 needed
- Left Output
- Jumpers
- (near J13) * Pin Diameter: 2.0-2.3mm
- (near J12) Stereo BTL Mode
  J6 - J10 = open
  J7 - J11 = open
  Mono PBTL Mode
  J6 - J10 = short
  J7 - J11 = short
- (near R49) 16.3A
- (near J13) * 3231-4-00-15-00-00-08-0
- Right Output
- Stereo BTL Mode
  M1 = L
  M2 = L
  Mono PBTL Mode
  M1 = L
  M2 = H
- * Master: Connect FREQ_ADJ with 10 kOhm to GND
  * Slave: Connect FREQ_ADJ with 0 Ohm to DVDD
- Assembly Instruction for Mono PBTL Mode
  * C32/R36 and C37 not populated (Input D)
  * C39/R42 and C40 not populated (Input C)
  * Place 0 Ohm resistor on pad C37 (Input D connected to GND)
  * Place 0 Ohm resistor on pad C40 (Input C connected to GND)

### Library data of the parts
C18 C22 C25 C32 C35 C39 = R82CC4470Z330J: CAP, Film, 4.7 µF, 50 V, +/- 5%, TH; Manufacturer: Kemet; Polarized: N; CompType: Capacitor; Value: 4.7uF; U/M: EA; Cap_F: 0.0000047; Tolerance_%: 5; Value1: Unknown; VDC_V: 50; Value2: 50V; TaMin_C: -55; TaMax_C: 105; Cap_Case: 7.2x7.2x13mm; AEC Category: Q200
C19 C23 C26 C29 C30 C36 C60 C66 C72 C73 = C1608X7R1H104K: as C2 on sheet PMP11769RevC - System
C20 C31 = C1005C0G1H220J050BA: CAP, CERM, 22 pF, 50 V, +/- 5%, C0G/NP0, 0402; Manufacturer: TDK; Polarized: N; CompType: Capacitor; Value: 22pF; U/M: EA; Cap_F: 0.000000000022; Tolerance_%: 5; Value1: Unknown; VDC_V: 50; Value2: 50V; TaMin_C: -55; TaMax_C: 125; AEC Category: Q200
C21 C24 C28 C37 C38 C40 = C1608C0G1H101J: CAP, CERM, 100 pF, 50 V, +/- 5%, C0G/NP0, 0603; Manufacturer: TDK; Polarized: N; CompType: Capacitor; Value: 100pF; U/M: EA; Cap_F: 0.0000000001; Tolerance_%: 5; ESR_ohm: 0.1679; Value1: 0.1679 ohm; VDC_V: 50; Value2: 50V; TaMin_C: -55; TaMax_C: 125; AEC Category: Q200
C27 = R82DC3100DQ50J: CAP, Film, 0.1 µF, 63 V, +/- 5%, TH; Manufacturer: Kemet; Polarized: N; CompType: Capacitor; Value: 0.1uF; U/M: EA; Cap_F: 0.0000001; Tolerance_%: 5; Value1: Unknown; VDC_V: 63; Value2: 63V; TaMin_C: -55; TaMax_C: 105; Cap_Case: 7.2x2.5x6.5mm; AEC Category: Q200
C33 = R82DC3220DQ60J: CAP, Film, 0.22 µF, 63 V, +/- 5%, TH; Manufacturer: Kemet; Polarized: N; CompType: Capacitor; Value: 0.22uF; U/M: EA; Cap_F: 0.00000022; Tolerance_%: 5; Value1: Unknown; VDC_V: 63; Value2: 63V; TaMin_C: -55; TaMax_C: 105; Cap_Case: 7.2x2.5x6.5mm; AEC Category: Q200
C34 = R82DC3150AA60J: CAP, Film, 0.15 µF, 63 V, +/- 5%, TH; Manufacturer: Kemet; Polarized: N; CompType: Capacitor; Value: 0.15uF; U/M: EA; Cap_F: 0.00000015; Tolerance_%: 5; Value1: Unknown; VDC_V: 63; Value2: 63V; TaMin_C: -55; TaMax_C: 105; Cap_Case: 7.2x2.5x6.5mm; AEC Category: Q200
C41 C61 C68 C74 = C1608X7R1H103K: CAP, CERM, 0.01 µF, 50 V, +/- 10%, X7R, 0603; Manufacturer: TDK; Polarized: N; CompType: Capacitor; Value: 0.01uF; U/M: EA; Cap_F: 0.00000001; Tolerance_%: 10; ESR_ohm: 0.0539; Value1: 0.0539 ohm; VDC_V: 50; Value2: 50V; TaMin_C: -55; TaMax_C: 125; AEC Category: Q200
C42-C45 = UPW1H821MHD6: CAP, AL, 560 µF, 40 V, +/- 20%, 0.045 ohm, TH; Manufacturer: Nichicon; Polarized: Y; CompType: Capacitor; Value: 560uF; U/M: EA; Cap_F: 0.00056; Tolerance_%: 20; VDC_V: 40; ESR_ohm: 0.045; IRMS_A: 2.0; TaMin_C: -55; TaMax_C: 105; Cap_Case: 18x15mm; AEC Category: Q200; AEC Qualified: N
C46-C53 = UMK107AB7105KA-T: CAP, CERM, 1 µF, 50 V, +/- 10%, X7R, 0603; Manufacturer: Taiyo Yuden; Polarized: N; CompType: Capacitor; Value: 1uF; U/M: EA; Cap_F: 0.000001; Tolerance_%: 10; Value1: Unknown; VDC_V: 50; TaMin_C: -55; TaMax_C: 125; AEC Category: Q200
C54 C55 C64 C65 = GRM188R71H333KA61D: CAP, CERM, 0.033 µF, 50 V, +/- 10%, X7R, 0603; Manufacturer: MuRata; Polarized: N; CompType: Capacitor; Value: 0.033uF; U/M: EA; Cap_F: 0.000000033; Tolerance_%: 10; Value1: Unknown; VDC_V: 50; Value2: 50V; TaMin_C: -55; TaMax_C: 125; AEC Category: Q200
C56 C62 C69 C75 = PHE426HB7100JR06: CAP, Film, 1 µF, 250 V, +/- 5%, TH; Manufacturer: Kemet; Polarized: N; CompType: Capacitor; Value: 1uF; U/M: EA; Cap_F: 0.000001; Tolerance_%: 5; Value1: Unknown; VDC_V: 250; Value2: 250V; TaMin_C: -55; TaMax_C: 105; Cap_Case: 18x9.5x17.5mm; AEC Category: Q200
C57 C63 C70 C76 = C1608C0G2A102J: CAP, CERM, 1000 pF, 100 V, +/- 5%, C0G/NP0, 0603; Manufacturer: TDK; Polarized: N; CompType: Capacitor; Value: 1000pF; U/M: EA; Cap_F: 0.000000001; Tolerance_%: 5; ESR_ohm: 0.0589; Value1: 0.0589 ohm; VDC_V: 100; Value2: 100V; TaMin_C: -55; TaMax_C: 125; AEC Category: Q200
C58 C59 C71 = C1608X7R1E105K080AB: as C1 on sheet PMP11769RevC - System
C67 = C3225X7R1E106M: CAP, CERM, 10 µF, 25 V, +/- 20%, X7R, 1210; Manufacturer: TDK; Polarized: N; CompType: Capacitor; Value: 10uF; U/M: EA; Cap_F: 0.00001; Tolerance_%: 20; ESR_ohm: 0.0027; Value1: 0.0027 ohm; VDC_V: 25; Value2: 25V; IRMS_A: 3; TaMin_C: -55; TaMax_C: 125; AEC Category: Q200
J5 = 971: RCA Jack, Red, R/A, TH; Manufacturer: Keystone; SymbolCreator: Altium; CompType: Phono Jack; U/M: EA
J6 J7 J17 = 61300311121: as J2 on sheet PMP11769RevC - System
J8 = 972: RCA Jack, Black, R/A, TH; Manufacturer: Keystone; SymbolCreator: Altium; CompType: Phono Jack; U/M: EA
J9 J13 = 973 582-101: TEST SOCKET, PCB, 4MM, RED; Manufacturer: Hirschmann; SymbolCreator: a0799628
J10 J11 J14 J15 = H3492-01: Pin Receptacle, Dia 4 mm, Gold, TH; Manufacturer: Harwin; Gender: Female; Current_A: 20
J12 J16 = 973 582-100: TEST SOCKET, PCB, 4MM, BLACK; Manufacturer: Hirschmann; SymbolCreator: a0799628
L5-L8 = SER2918H-103KL: Inductor, Shielded E Core, Ferrite, 10 µH, 28 A, 0.0026 ohm, SMD; Manufacturer: Coilcraft; Value: 10uH; Ind_H: 10.0E-6; Imax_A: 28; Irms: 28A @ 40C rise; Isat: 32.1A @ 30% inductance drop; DCR_ohm: 0.0026; Value2: 28A; AEC Category: Q200
R19 R20 R26 R36 R37 R42 = CRCW0603100RFKEA: as R4 on sheet PMP11769RevC - System
R21 R27 R38 R39 = CRCW040210K0FKED: RES, 10.0 k, 1%, 0.063 W, 0402; Manufacturer: Vishay-Dale; CompType: Resistor; Value: 10.0k; Res_ohm: 10000; Value_Code: 10k0; Tolerance_%: 1; Power_W: 0.063; Value2: 0.063W; VDC_V: 50; TempCo: 100 ppm/C; EIA_Code: E96; U/M: EA; AEC Category: Q200
R22 = CRCW060313K7FKEA: RES, 13.7 k, 1%, 0.1 W, 0603; Manufacturer: Vishay-Dale; CompType: Resistor; Value: 13.7k; Res_ohm: 13700; Value_Code: 13k7; Tolerance_%: 1; Power_W: 0.1; Value2: 0.1W; VDC_V: 75; TempCo: 100 ppm/C; EIA_Code: E96; U/M: EA; AEC Category: Q200
R23 R32 R40 R54 = CRCW06030000Z0EA: RES, 0, 5%, 0.1 W, 0603; Manufacturer: Vishay-Dale; CompType: Resistor; Value: 0; Value_Code: 0000; Tolerance_%: 5; Power_W: 0.1; Value2: 0.1W; VDC_V: 75; TempCo: 200 ppm/C; EIA_Code: E24; U/M: EA; AEC Category: Q200
R24 R41 = CRCW0603100KFKEA: RES, 100 k, 1%, 0.1 W, 0603; Manufacturer: Vishay-Dale; CompType: Resistor; Value: 100k; Res_ohm: 100000; Tolerance_%: 1; Power_W: 0.1; Value2: 0.1W; VDC_V: 75; TempCo: 100 ppm/C; EIA_Code: E96; U/M: EA; AEC Category: Q200
R25 R30 R43 R53 = CRCW060310K0FKEA: as R3 on sheet PMP11769RevC - System
R28 R33 = CRCW060320K0FKEA: RES, 20.0 k, 1%, 0.1 W, 0603; Manufacturer: Vishay-Dale; CompType: Resistor; Value: 20.0k; Res_ohm: 20000; Value_Code: 20k0; Tolerance_%: 1; Power_W: 0.1; Value2: 0.1W; VDC_V: 75; TempCo: 100 ppm/C; EIA_Code: E96; U/M: EA; AEC Category: Q200
R29 = PTD902-2015F-A103: Trimmer Potentiometer, 10K Ohm, 0.025W, TH; Manufacturer: Bourns; SymbolCreator: Altium
R31 R44 = CRCW060324K3FKEA: RES, 24.3 k, 1%, 0.1 W, 0603; Manufacturer: Vishay-Dale; CompType: Resistor; Value: 24.3k; Res_ohm: 24300; Value_Code: 24k3; Tolerance_%: 1; Power_W: 0.1; Value2: 0.1W; VDC_V: 75; TempCo: 100 ppm/C; EIA_Code: E96; U/M: EA; AEC Category: Q200
R34 = CRCW06034K53FKEA: RES, 4.53 k, 1%, 0.1 W, 0603; Manufacturer: Vishay-Dale; CompType: Resistor; Value: 4.53k; Res_ohm: 4530; Value_Code: 4k53; Tolerance_%: 1; Power_W: 0.1; Value2: 0.1W; VDC_V: 75; TempCo: 100 ppm/C; EIA_Code: E96; U/M: EA; AEC Category: Q200
R35 = CRCW06036K81FKEA: RES, 6.81 k, 1%, 0.1 W, 0603; Manufacturer: Vishay-Dale; CompType: Resistor; Value: 6.81k; Res_ohm: 6810; Value_Code: 6k81; Tolerance_%: 1; Power_W: 0.1; Value2: 0.1W; VDC_V: 75; TempCo: 100 ppm/C; EIA_Code: E96; U/M: EA; AEC Category: Q200
R45-R48 R50-R52 = CRCW06033R32FKEA: RES, 3.32, 1%, 0.1 W, 0603; Manufacturer: Vishay-Dale; CompType: Resistor; Value: 3.32; Value_Code: 3R32; Tolerance_%: 1; Power_W: 0.1; Value2: 0.1W; VDC_V: 75; TempCo: 100 ppm/C; EIA_Code: E96; U/M: EA; AEC Category: Q200
R49 = CRCW060322K1FKEA: RES, 22.1 k, 1%, 0.1 W, 0603; Manufacturer: Vishay-Dale; CompType: Resistor; Value: 22.1k; Res_ohm: 22100; Value_Code: 22k1; Tolerance_%: 1; Power_W: 0.1; Value2: 0.1W; VDC_V: 75; TempCo: 100 ppm/C; EIA_Code: E96; U/M: EA; AEC Category: Q200
U5 U7 = OPA1662AIDRQ1: Automotive Catalog, Sound Plus, Low-Power, Low-Noise and Distortion, Audio Operational Amplifier, 3 to 36 V, -40 to 85 degC, 8-pin SOIC (D0008A), Green (RoHS & no Sb/Br); Manufacturer: Texas Instruments; Alternate PartNumber: Equivalent; CMRR(Min)(dB): 106; GBW(Typ)(MHz): 22; IIB(Max)(pA): 1200000; Iq per channel(Max)(mA): 1.8; Number of Channels: 2; Packing: LARGE T&R; Slew Rate(Typ)(V/us): 17; Sub Family: High Supply Voltage Amplifier (>=30V), Low Noise Amp (<=10nV/rtHz), Precision Amplifier; Total Supply Voltage(Max)(+5V is 5, +/-5V is 10): 36; Total Supply Voltage(Min)(+5V is 5, +/-5V is 10): 3; Vio (25C)(Max)(mV): 1.5
U6 = OPA1662AIDGKRQ1: Automotive Catalog, Sound Plus, Low-Power, Low-Noise and Distortion, Audio Operational Amplifier, 3 to 36 V, -40 to 85 degC, 8-pin SOP (DGK0008A), Green (RoHS & no Sb/Br); Manufacturer: Texas Instruments; Alternate PartNumber: Equivalent; CMRR(Min)(dB): 106; GBW(Typ)(MHz): 22; IIB(Max)(pA): 1200000; Iq per channel(Max)(mA): 1.8; Number of Channels: 2; Packing: LARGE T&R; Slew Rate(Typ)(V/us): 17; Sub Family: High Supply Voltage Amplifier (>=30V), Low Noise Amp (<=10nV/rtHz), Precision Amplifier; Total Supply Voltage(Max)(+5V is 5, +/-5V is 10): 36; Total Supply Voltage(Min)(+5V is 5, +/-5V is 10): 3; Vio (25C)(Max)(mV): 1.5
U8 = TPA3251D2DDVR: 150W Stereo/300W MONO PurePath HD Analog-input Power Stage, DDV0044D; Manufacturer: Texas Instruments; SymbolCreator: Altium; CompType: IC; U/M: EA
